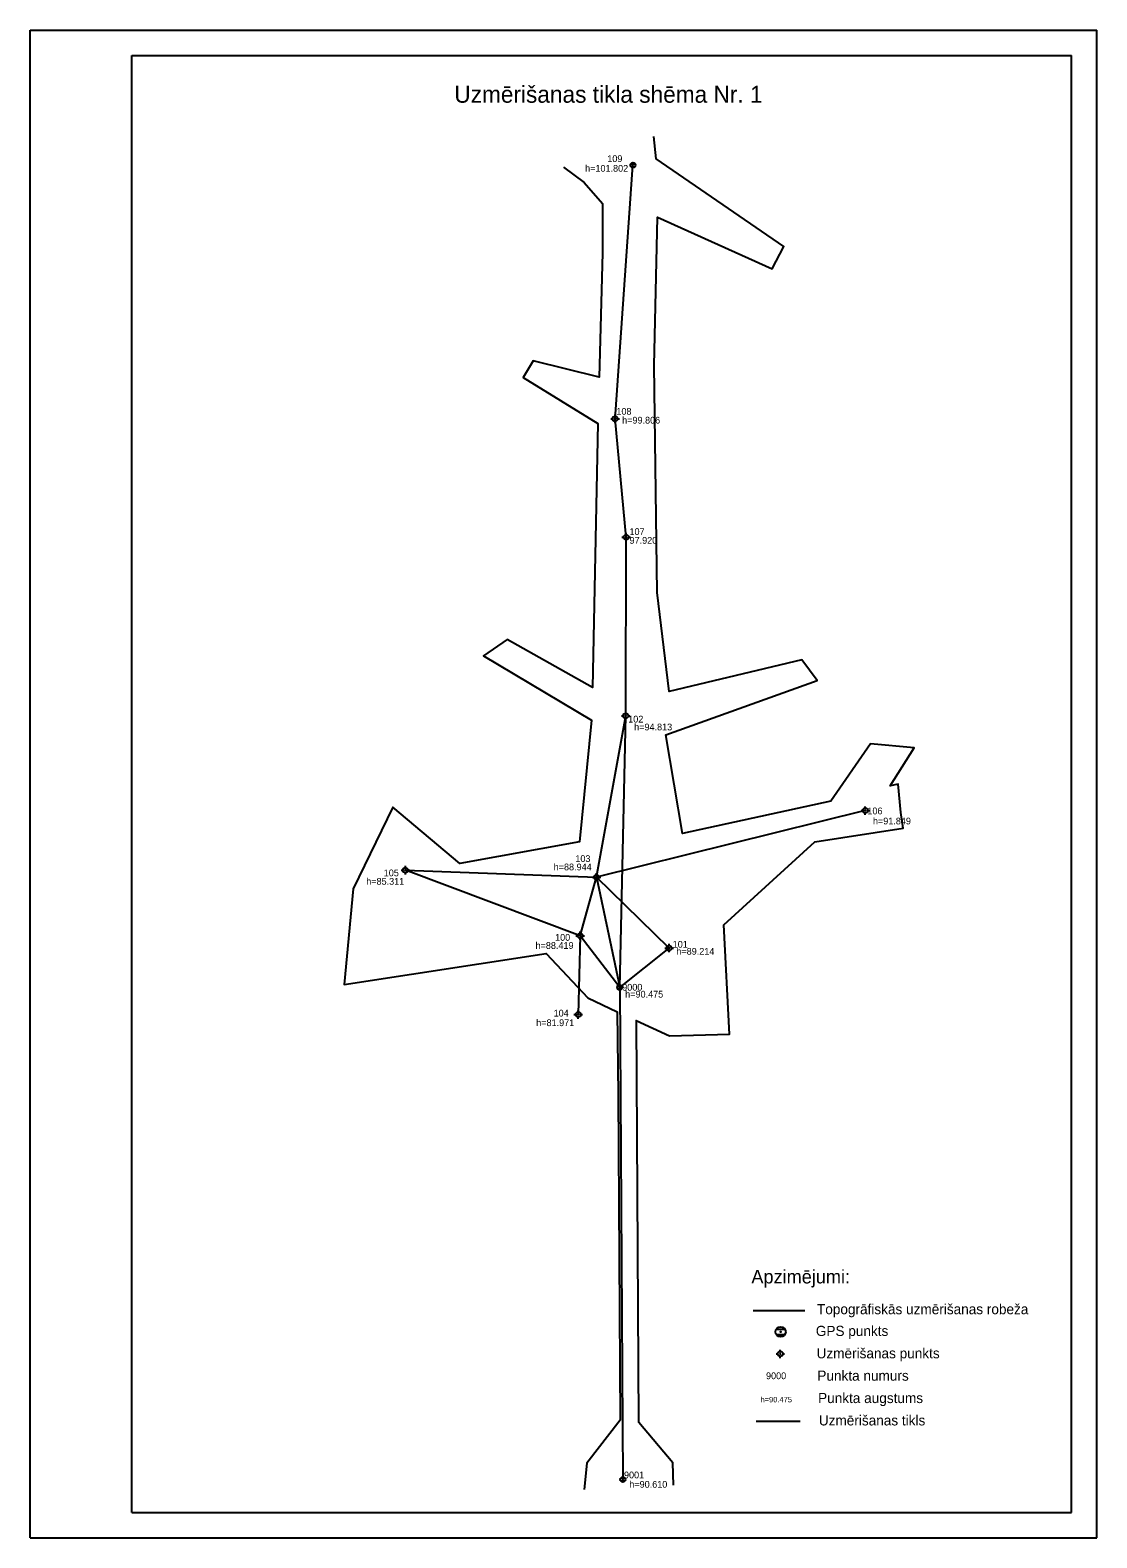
# Model space of a CAD drawing. Extents: x 615281 to 615911, y 263112 to 264003.
import ezdxf

# ---------------------------------------------------------------- set-up
doc = ezdxf.new("R2010")
doc.units = 0
for name, color, linetype in [('Level 19', 7, 'Continuous'), ('Level 25', 7, 'Continuous'), ('Level 63', 7, 'Continuous'), ('Level 9', 7, 'Continuous')]:
    doc.layers.add(name, color=color, linetype=linetype)

msp = doc.modelspace()

# ---------------------------------------------------------------- linework, layer by layer
at = {"layer": 'Level 19'}
for p, q in [((615626.06, 263773.35), (615636.56, 263923.23)), ((615635.26, 263923.98), (615637.86, 263923.98)), ((615635.26, 263922.48), (615637.86, 263922.48)), ((615623.56, 263773.35), (615624.56, 263773.35)), ((615626.06, 263774.86), (615626.06, 263775.86)), ((615632.6, 263703.31), (615626.06, 263773.35)), ((615626.06, 263770.86), (615626.06, 263771.86)), ((615627.56, 263773.35), (615628.56, 263773.35)), ((615630.1, 263703.31), (615631.1, 263703.31)), ((615632.31, 263597.85), (615632.6, 263703.31)), ((615632.6, 263704.81), (615632.6, 263705.81)), ((615632.6, 263700.81), (615632.6, 263701.81)), ((615634.1, 263703.31), (615635.1, 263703.31)), ((615615.07, 263502.37), (615632.31, 263597.85)), ((615628.81, 263437.35), (615632.31, 263597.85)), ((615629.81, 263597.85), (615630.81, 263597.85)), ((615632.31, 263599.35), (615632.31, 263600.35)), ((615632.31, 263595.35), (615632.31, 263596.35)), ((615633.81, 263597.85), (615634.81, 263597.85)), ((615773.83, 263541.8), (615615.07, 263502.37)), ((615771.33, 263541.8), (615772.33, 263541.8)), ((615773.83, 263543.3), (615773.83, 263544.3)), ((615773.83, 263539.3), (615773.83, 263540.3)), ((615775.33, 263541.8), (615776.33, 263541.8)), ((615499.72, 263506.56), (615500.72, 263506.56)), ((615502.22, 263508.06), (615502.22, 263509.06)), ((615605.4, 263467.88), (615502.22, 263506.56)), ((615502.22, 263506.56), (615615.07, 263502.37)), ((615502.22, 263504.06), (615502.22, 263505.06)), ((615503.72, 263506.56), (615504.72, 263506.56)), ((615615.07, 263503.87), (615615.07, 263504.87)), ((615605.4, 263467.88), (615615.07, 263502.37)), ((615612.57, 263502.37), (615613.57, 263502.37)), ((615615.07, 263502.37), (615628.81, 263437.35)), ((615657.95, 263460.58), (615615.07, 263502.37)), ((615615.07, 263499.87), (615615.07, 263500.87)), ((615616.57, 263502.37), (615617.57, 263502.37)), ((615605.4, 263469.38), (615605.4, 263470.38)), ((615602.9, 263467.88), (615603.9, 263467.88)), ((615605.4, 263467.88), (615604.26, 263421.26)), ((615628.81, 263437.35), (615605.4, 263467.88)), ((615605.4, 263465.38), (615605.4, 263466.38)), ((615606.9, 263467.88), (615607.9, 263467.88)), ((615628.81, 263437.35), (615657.95, 263460.58)), ((615655.46, 263460.58), (615656.46, 263460.58)), ((615657.95, 263462.08), (615657.95, 263463.08)), ((615659.46, 263460.58), (615660.46, 263460.58)), ((615657.95, 263458.08), (615657.95, 263459.08)), ((615627.51, 263438.1), (615630.11, 263438.1)), ((615627.51, 263436.6), (615630.11, 263436.6)), ((615601.76, 263421.26), (615602.76, 263421.26)), ((615604.26, 263422.76), (615604.26, 263423.76)), ((615604.26, 263418.76), (615604.26, 263419.76)), ((615605.76, 263421.26), (615606.76, 263421.26)), ((615721.22, 263235.26), (615726.42, 263235.26)), ((615721.22, 263232.26), (615726.42, 263232.26)), ((615721.14, 263220.68), (615722.14, 263220.68)), ((615723.64, 263222.18), (615723.64, 263223.18)), ((615725.14, 263220.68), (615726.14, 263220.68)), ((615723.64, 263218.18), (615723.64, 263219.18)), ((615735.33, 263180.72), (615709.36, 263180.78)), ((615629.33, 263147.26), (615631.92, 263147.26)), ((615629.33, 263145.76), (615631.92, 263145.76))]:
    msp.add_line(p, q, dxfattribs=at)
for centre, radius in [((615636.56, 263923.23), 1.5), ((615636.56, 263923.23), 0.08), ((615626.06, 263773.35), 1.5), ((615626.06, 263773.35), 0.2), ((615632.6, 263703.31), 1.5), ((615632.6, 263703.31), 0.2), ((615632.31, 263597.85), 1.5), ((615632.31, 263597.85), 0.2), ((615773.83, 263541.8), 1.5), ((615773.83, 263541.8), 0.2), ((615502.22, 263506.56), 1.5), ((615502.22, 263506.56), 0.2), ((615615.07, 263502.37), 1.5), ((615615.07, 263502.37), 0.2), ((615605.4, 263467.88), 1.5), ((615605.4, 263467.88), 0.2), ((615657.95, 263460.58), 1.5), ((615657.95, 263460.58), 0.2), ((615628.81, 263437.35), 1.5), ((615628.81, 263437.35), 0.08), ((615604.26, 263421.26), 1.5), ((615604.26, 263421.26), 0.2), ((615723.82, 263233.76), 3), ((615723.82, 263233.76), 0.16), ((615723.64, 263220.68), 1.5), ((615723.64, 263220.68), 0.2), ((615630.62, 263146.51), 1.5), ((615630.62, 263146.51), 0.08)]:
    msp.add_circle(centre, radius, dxfattribs=at)
at = {"layer": 'Level 25'}
msp.add_line((615707.54, 263246.31), (615738.1, 263246.31), dxfattribs=at)
for points in [[(615660.48, 263143.06), (615660.06, 263156.38), (615640.14, 263180.2), (615638.64, 263417.62), (615638.54, 263417.67), (615658.23, 263408.6), (615693.67, 263409.77), (615690.23, 263474.23), (615744.11, 263523.27), (615796.12, 263531.37), (615794.91, 263540.72), (615793.18, 263557.51), (615788.51, 263556.44), (615802.67, 263578.88), (615776.8, 263581.31), (615753.45, 263547.45), (615665.88, 263528.3), (615655.92, 263586.61), (615745.35, 263618.77), (615736.41, 263630.88), (615657.94, 263612.09), (615650.82, 263670.67), (615649.19, 263804.75), (615651.03, 263892.42), (615718.86, 263862), (615725.65, 263875.12), (615650.27, 263927.03), (615649, 263940.22)], [(615595.57, 263922.06), (615607.77, 263913.06), (615618.57, 263900.65), (615618.57, 263871.49), (615616.58, 263797.94), (615577.64, 263807.5), (615571.84, 263797.84), (615615.86, 263770.49), (615612.63, 263614.58), (615562.27, 263642.95), (615548.33, 263633.18), (615612.09, 263595.19), (615604.96, 263523.33), (615534.36, 263510.48), (615494.74, 263543.92), (615471.27, 263495.58), (615466.1, 263438.94), (615585.43, 263457.4), (615609.91, 263431.16), (615627.32, 263422.83), (615627.77, 263373.74), (615629.09, 263181.57), (615609.32, 263156.19), (615607.83, 263140.62)]]:
    msp.add_lwpolyline(points, dxfattribs=at)
at = {"layer": 'Level 63'}
for p, q in [((615280.57, 263112.02), (615280.57, 264003.02)), ((615280.57, 264003.02), (615910.57, 264003.02)), ((615910.57, 263112.02), (615910.57, 264003.02)), ((615340.57, 263127.02), (615340.57, 263988.02)), ((615340.57, 263988.02), (615895.57, 263988.02)), ((615895.57, 263127.02), (615895.57, 263988.02)), ((615340.57, 263127.02), (615895.57, 263127.02)), ((615280.57, 263112.02), (615910.57, 263112.02))]:
    msp.add_line(p, q, dxfattribs=at)
at = {"layer": 'Level 9'}
msp.add_line((615628.81, 263437.35), (615630.62, 263146.51), dxfattribs=at)

# ---------------------------------------------------------------- texts
at = {"layer": 'Level 19'}
for s, height, p in [('h=101.802', 4, (615608.33, 263919.37)), (' 109', 4, (615619.94, 263925.07)), (' 108', 4, (615625.32, 263775.75)), ('h=99.806', 4, (615630.21, 263770.51)), (' 97.920', 4, (615633.1, 263699.5)), (' 107', 4, (615633.06, 263704.68)), (' 102', 4, (615632.31, 263593.85)), ('h=94.813', 4, (615637.3, 263589.21)), (' 106', 4, (615773.58, 263539.62)), ('h=91.849', 4, (615778.33, 263533.64)), (' 103', 4, (615601.07, 263511.42)), (' 105', 4, (615487.9, 263502.99)), ('h=88.944', 4, (615589.77, 263506.49)), ('h=85.311', 4, (615479.05, 263497.99)), (' 100', 4, (615589.12, 263464.85)), ('h=88.419', 4, (615579.05, 263460.08)), (' 101', 4, (615658.58, 263460.78)), ('h=89.214', 4, (615662.22, 263456.63)), (' 9000', 4, (615628.77, 263435.4)), ('h=90.475', 4, (615632, 263431.3)), (' 104', 4, (615588.24, 263420.1)), ('h=81.971', 4, (615579.45, 263414.44)), (' 9000', 4, (615713.71, 263205.78)), (' h=90.475', 3.2, (615710.71, 263192.11)), (' 9001', 4, (615629.81, 263147.19)), ('h=90.610', 4, (615634.43, 263141.65))]:
    msp.add_text(s, height=height, dxfattribs=at).set_placement(p)
at = {"layer": 'Level 63'}
for s, height, p in [('Uzmērišanas tikla shēma Nr. 1', 10, (615531.09, 263960.12)), ('Apzimējumi:', 8, (615706.55, 263262.37)), ('Topogrāfiskās uzmērišanas robeža', 6, (615745.28, 263244.17)), ('GPS punkts', 6, (615744.61, 263231.31)), ('Uzmērišanas punkts', 6, (615745.06, 263218.1)), ('Punkta numurs', 6, (615745.51, 263204.88)), ('Punkta augstums', 6, (615745.95, 263191.67)), ('Uzmērišanas tikls', 6, (615746.4, 263178.46))]:
    msp.add_text(s, height=height, dxfattribs=at).set_placement(p)

doc.saveas('drawing.dxf')
